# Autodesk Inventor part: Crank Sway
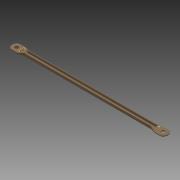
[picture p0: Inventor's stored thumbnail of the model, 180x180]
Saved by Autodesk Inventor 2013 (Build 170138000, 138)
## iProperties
Created: 2006-03
Part Number: Crank Sway
Document SubType Name: Modeling
Designer: Autodesk, Inc.
Material: Stainless Steel, 440C
Mass: 132.412 g
Surface Area: 221.126 cm^2
Volume: 17.0854 cm^3
Density: 7.75 g/cm^3
Author: Autodesk, Inc.
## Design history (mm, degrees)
sketch "Sketch1"
  geometry: L1 (0, 0)-(0, 1.6); L2 (0, 1.6)-(4.6, 1.6); L3 (4.6, 1.6)-(4.6, 8); L4 (4.6, 8)-(6.2, 8); L5 (6.2, 8)-(6.2, 1.5); L6 (4.7, 0)-(0, 0); L7 (0, 9.662)-(0, -1.973) reference; L8 (-4.6, 1.6)-(-4.6, 8); L9 (-4.6, 8)-(-6.2, 8); L10 (-6.2, 8)-(-6.2, 1.5); L11 (0, 1.6)-(-4.6, 1.6); L12 (-4.7, 0)-(0, 0); A1 r 1.5 centre (4.7, 1.5) between (4.7, 0) and (6.2, 1.5); A2 r 1.5 centre (-4.7, 1.5) between (-6.2, 1.5) and (-4.7, 0)
  constraints: 22 end point, 6 symmetric about line, 4 parallel, 4 point on circle, 2 centre point, 2 perpendicular, 2 tangent, 1 vertical, 1 other
  dimensions: "d1" = 4.6 distance between parallel lines of L3 L1; "d2" = 8 distance between parallel lines of L6 L4; "d3" = 1.6 distance between parallel lines of L5 L3; "d4" = 1.5 radius of A1
extrude "Extrusion1" new body sketch "Sketch1" distance "d5" = 175; taper "d6" = 0 deg
workplane "Work Plane1"
sketch "Sketch2"
  geometry: L1 (-1.6, 0)-(9.6, 0) reference; L2 (3, 12)-(5, 12); L3 (5, 12)-(5, -12); L4 (5, -12)-(3, -12); L5 (3, -12)-(3, 12); L6 (3, 12)-(5, -12); L7 (1.5, 6.2)-(8, 6.2) reference; L8 (8, -6.2)-(1.5, -6.2) reference; L9 (0, -4.7)-(0, 4.7) reference; 2 further points
  constraints: 10 end point, 2 midpoint, 2 parallel, 1 horizontal, 1 perpendicular
  dimensions: "d8" = 4 distance from line of point (4, 0) L9; "d9" = 2 distance of L2.start L2.end; "d10" = 24 distance of L2.end L3.end
loft "Loft1" sketch "Sketch2" dims "d11" = 0, "d12" = 90 deg, "d13" = 0, "d14" = 90 deg
  node "Edges1"
sketch "Sketch3"
  geometry: L1 (2, 12.374)-(2, 18.469) reference; L2 (2, 19.993)-(0, 19.993) reference; L3 (2, 18.469)-(2, 19.993) reference; L4 (2, 3.612)-(2, 12.374) reference; L5 (2, -2.483)-(2, 3.612) reference; L6 (2, -4.007)-(2, -2.483) reference; L7 (0, -4.007)-(2, -4.007) reference; L8 (0, 0)-(0, -4.007) reference; L9 (0, 15.986)-(0, 0) reference; L10 (0, 19.993)-(0, 15.986) reference; 1 further point
extrude "Extrusion2" join sketch "Sketch3" distance "d15" = 20; taper "d16" = 0 deg
sketch "Sketch4"
  geometry: L1 (-49.747, 12)-(250.958, 12) reference; L2 (0, 24)-(0, 0); A1 r 14 centre (7.211, 12) between (0, 24) and (0, 0); 1 further point
  constraints: 3 point on circle, 2 end point, 1 centre point, 1 perpendicular, 1 point on line
  dimensions: "d17" = 14 radius of A1
extrude "Extrusion3" join sketch "Sketch4" stored distance "d18" = 20; taper "d19" = 0 deg
sketch "Sketch5"
  geometry: L1 (-69.747, 4.381)-(230.958, 4.381) reference; L2 (0, 12.374)-(0, -3.612) reference; C1 r 5 at (-14, 4.381); 1 further point
  constraints: 1 centre point, 1 point on line
  dimensions: "d20" = 10 diameter of C1; "d21" = 14 distance from line of C1.centre L2
extrude "Extrusion4" cut sketch "Sketch5" stored distance "d22" = 20; taper "d23" = 0 deg
mirror "Mirror1"
body "Solid1"
other parameters: "d7" = 13
